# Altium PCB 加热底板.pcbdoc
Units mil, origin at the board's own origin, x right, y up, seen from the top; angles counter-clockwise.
Board outline 3503.93 x 3503.63 mil, 2 copper layers (Top Layer, Bottom Layer); 2 components, 2 nets, 6 pads, 0 vias.
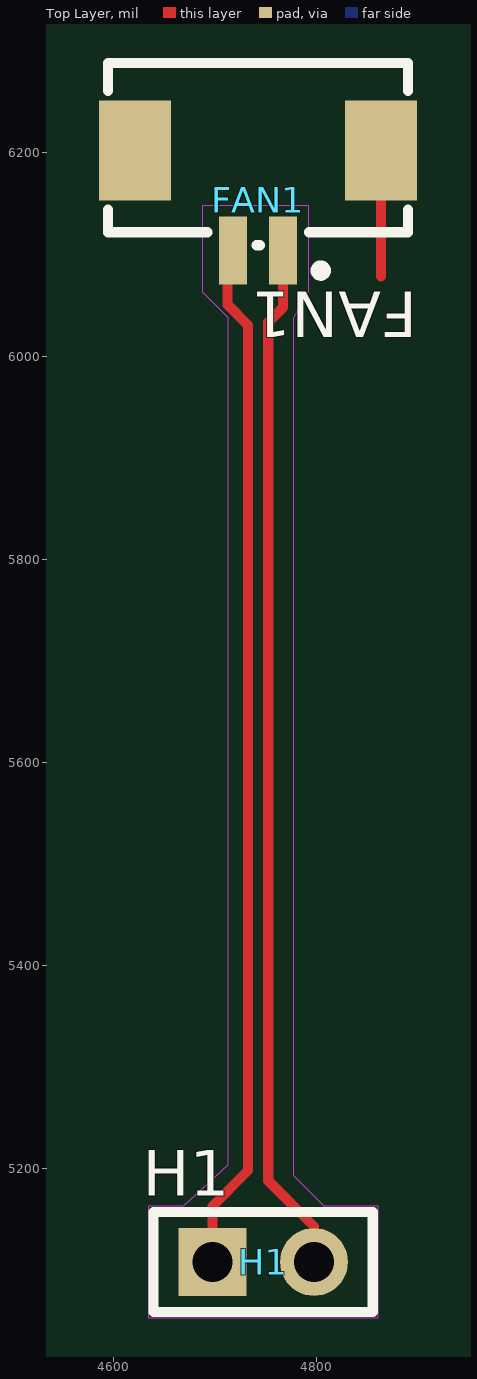
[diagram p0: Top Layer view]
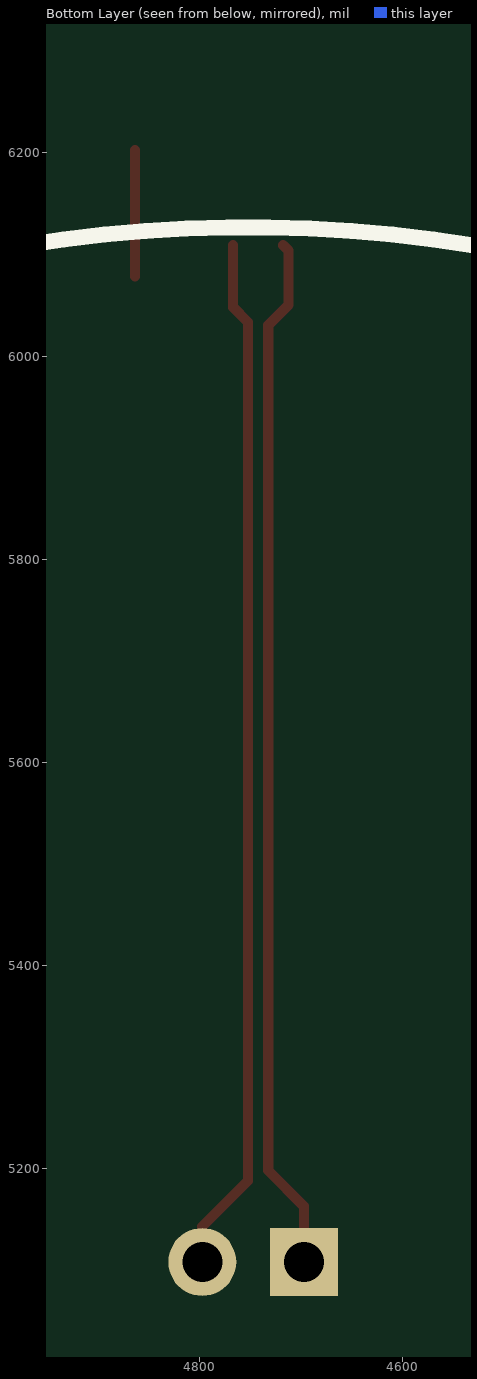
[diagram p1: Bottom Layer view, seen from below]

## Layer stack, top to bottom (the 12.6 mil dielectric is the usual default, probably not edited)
Top Layer: signal copper (thickness not stored)
Dielectric: dielectric 12.6, FR-4, Dk 4.8
Bottom Layer: signal copper (thickness not stored)

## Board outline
6503.93,4751.97 ccw(c4751.97,4751.96) 3000,4751.96 ccw(c4751.97,4751.96)

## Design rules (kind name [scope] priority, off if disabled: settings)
BoardOutlineClearance copperThickness1oz [All] p0: genericclearance=10 ignorepadtopadclearanceinfootprint=FALSE except(0: Arc-SplitContinuation Track-SplitContinuation SMDPad-SplitContinuation THPad-SplitContinuation Via-SplitContinuation Fill-SplitContinuation Poly-SplitContinuation Region-SplitContinuation Text-SplitContinuation; 6: Track-CutoutEdge SMDPad-CutoutEdge THPad-CutoutEdge Via-CutoutEdge Region-CutoutEdge; 11.8: Track-OutlineEdge SMDPad-OutlineEdge THPad-OutlineEdge Via-OutlineEdge Fill-OutlineEdge Region-OutlineEdge Poly-OutlineEdge Text-OutlineEdge Fill-CutoutEdge)
BoardOutlineClearance copperThickness2oz [All] p0: genericclearance=10 ignorepadtopadclearanceinfootprint=FALSE except(0: Arc-SplitContinuation Track-SplitContinuation SMDPad-SplitContinuation THPad-SplitContinuation Via-SplitContinuation Fill-SplitContinuation Poly-SplitContinuation Region-SplitContinuation Text-SplitContinuation; 6: Track-CutoutEdge SMDPad-CutoutEdge THPad-CutoutEdge Via-CutoutEdge Region-CutoutEdge; 11.8: Track-OutlineEdge SMDPad-OutlineEdge THPad-OutlineEdge Via-OutlineEdge Fill-OutlineEdge Region-OutlineEdge Poly-OutlineEdge Text-OutlineEdge Fill-CutoutEdge)
Clearance copperThickness1oz [(InNet('GND') OR InNet('NTC'))] p1: gap=7 ignorepadtopadclearanceinfootprint=FALSE except(4: Track-Track; 6: Track-SMDPad SMDPad-SMDPad Track-THPad SMDPad-THPad THPad-THPad Track-Via SMDPad-Via THPad-Via Via-Via SMDPad-Fill THPad-Fill Via-Fill Fill-Fill Track-Region SMDPad-Region THPad-Region Via-Region Region-Region Track-Poly SMDPad-Poly THPad-Poly Via-Poly Fill-Poly Region-Poly Poly-Poly Track-Text SMDPad-Text THPad-Text Via-Text Fill-Text Region-Text Poly-Text Text-Text; 6.9: Track-Hole SMDPad-Hole THPad-Hole Via-Hole Fill-Hole Region-Hole Poly-Hole Text-Hole Sheet-Hole; 11.8: Track-Fill Fill-Region Track-Sheet SMDPad-Sheet THPad-Sheet Via-Sheet Fill-Sheet Region-Sheet Poly-Sheet Text-Sheet)
Clearance copperThickness2oz [All] p1: gap=7 ignorepadtopadclearanceinfootprint=FALSE except(6: Track-SMDPad SMDPad-SMDPad Track-THPad SMDPad-THPad THPad-THPad Track-Via SMDPad-Via THPad-Via Via-Via SMDPad-Fill THPad-Fill Via-Fill Fill-Fill Track-Region SMDPad-Region THPad-Region Via-Region Region-Region Track-Poly SMDPad-Poly THPad-Poly Via-Poly Fill-Poly Region-Poly Poly-Poly Track-Text SMDPad-Text THPad-Text Via-Text Fill-Text Region-Text Poly-Text Text-Text; 6.9: Track-Hole SMDPad-Hole THPad-Hole Via-Hole Fill-Hole Region-Hole Poly-Hole Text-Hole Sheet-Hole; 8: Track-Track; 11.8: Track-Fill Fill-Region Track-Sheet SMDPad-Sheet THPad-Sheet Via-Sheet Fill-Sheet Region-Sheet Poly-Sheet Text-Sheet)
DiffPairsRouting differentialPair [All] p1: maxuncoupledlength=10 minlimit=6 maxlimit=6 mostfreqgap=6 toplayer_minwidth=5 toplayer_prefwidth=10 toplayer_maxwidth=100 bottomlayer_minwidth=5 bottomlayer_prefwidth=10 bottomlayer_maxwidth=100
PasteMaskExpansion pasteMaskExpansion [All] p1: expansion=0
PlaneConnect innerPlane [All] p1: planeconnectstyle=Relief reliefexpansion=20 reliefentries=4 reliefconductorwidth=10 reliefairgap=10
PolygonConnect copperRegion [All] p1: connectstyle=Relief reliefentries=4 reliefconductorwidth=10 polygonreliefangle="90 Angle" airgapwidth=10
RoutingVias viaSize [All] p1: viastyle="Through Hole" holewidth=12.0078 minholewidth=11.811 maxholewidth=248.0314 width=24.0158 minwidth=19.685 maxwidth=393.7008
SolderMaskExpansion solderMaskExpansion [All] p1: useseparateexpansions=TRUE expansion=2 expansionbottom=2
Width copperThickness1oz [All] p1: maxlimit=100 minlimit=5 preferedwidth=10
Width copperThickness2oz [All] p1: maxlimit=100 minlimit=8 preferedwidth=10

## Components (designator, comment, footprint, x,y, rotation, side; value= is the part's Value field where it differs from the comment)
FAN1 "WAFER-MX1.25-2PWB" CONN-SMD_2P-P1.25_XUNPU_WAFER-MX1.25-2PWB 4742.31,6153.31 r180 top
H1 "2.54-1*2P母" HDR-TH_2P-P2.54-V-F 4747.31,5108.31 r0 top

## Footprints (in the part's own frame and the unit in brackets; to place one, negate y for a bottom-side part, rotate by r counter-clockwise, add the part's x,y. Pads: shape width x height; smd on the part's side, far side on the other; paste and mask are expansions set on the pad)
CONN-SMD_2P-P1.25_XUNPU_WAFER-MX1.25-2PWB [mm]
  rect 0.7x1.7 smd: 1(-0.625,1.25) 2(0.625,1.25)
  rect 1.8x2.5 smd: 3(3.075,-1.25) 4(-3.075,-1.25)
  silkscreen extent -3.75,-3.43 3.75,1.88
HDR-TH_2P-P2.54-V-F [mm]
  rect 1.7x1.7 hole 1: 1(-1.27,0)
  round 1.7 hole 1: 2(1.27,0)
  silkscreen extent -2.74,-1.25 2.74,1.25

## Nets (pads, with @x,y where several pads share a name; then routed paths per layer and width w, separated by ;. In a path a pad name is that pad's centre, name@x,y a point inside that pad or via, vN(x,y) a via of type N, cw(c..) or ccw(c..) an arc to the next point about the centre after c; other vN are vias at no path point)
GND: FAN1.1 FAN1.4 H1.2 | length 1149.7
  Top Layer w10: FAN1.1@4766.92,6109.1 4766.92,6047.92 4752.31,6033.31 4752.31,5188.31 4797.31,5143.31 H1.2 ; 4863.38,6078.31 FAN1.4
NTC: FAN1.2 H1.1 | length 1025.8
  Top Layer w10: H1.1 4697.31,5163.31 4732.31,5198.31 4732.31,6030.38 4712.31,6050.38 4712.31,6103.7 FAN1.2@4717.71,6109.1
pads on no net: FAN1.3

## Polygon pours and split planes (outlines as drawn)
GND on Top Layer (solid, remove dead copper, pour order 0): 6120.67,4748.31 ccw(c4762.31,4748.31) 3403.96,4748.31 ccw(c4762.31,4748.31)

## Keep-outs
Top Layer:
  region: 4860.69,5053.59 4860.69,5163.43 4807.31,5163.31 4777.31,5193.31 4777.31,6037.71 4792.31,6063.31 4792.31,6148.14 4687.31,6148.14 4687.31,6063.31 4712.31,6038.31 4712.31,5203.5 4668.66,5163.43 4633.92,5163.43 4633.92,5053.59
Board Outline Layer:
  circle w7.87: c4751.97,4751.97 r1751.96

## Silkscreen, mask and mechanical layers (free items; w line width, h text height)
Top Silkscreen Layer:
  text "NTC B:3950 10k" at 4267.31,4873.31 h120
Bottom Silkscreen Layer:
  circle w15.75: c4751.97,4744.88 r1381.99
Mech6:
  lines w7.87: 4490.07,5593.04 cw(c4535.43,5447.38) 4687.99,5447.38 4687.99,5406.03 cw(c4535.43,5406.03) 4583.38,5261.2 ccw(c4751.97,4751.97) 4515.94,4270.26 ccw(c4535.43,4310.04) 4579.72,4310.04 4579.72,4354.35 ccw(c4535.43,4354.35) 4556.61,4393.24 cw(c4751.97,4751.97) 4406.34,4969.65 cw(c4535.43,4888.35) 4687.99,4888.35 4687.99,4751.97 ccw(c4751.97,4751.97) 4815.94,4751.97 4815.94,4888.35 cw(c4968.5,4888.35) 5097.59,4969.65 cw(c4751.97,4751.97) 4947.32,4393.25 ccw(c4968.5,4354.35) 4924.21,4354.35 4924.21,4310.04 ccw(c4968.5,4310.04) 4987.99,4270.26 ccw(c4751.96,4751.97) 4920.55,5261.2 cw(c4968.5,5406.03) 4815.94,5406.03 4815.94,5447.38 cw(c4968.5,5447.38) 5013.86,5593.04 cw(c4751.97,4751.97) 4958.13,3895.53 ccw(c4968.5,3852.47) 4924.21,3852.47 4924.21,3812.02 ccw(c4968.5,3812.02) 4978.44,3768.86 ccw(c4751.97,4751.97) 4940.06,5743.13 cw(c4968.5,5893.02) 4815.94,5893.02 4815.94,5933.06 cw(c4968.5,5933.07) 4996.01,6083.12 cw(c4751.97,4751.97) 5022.63,3425.96 5022.63,3300.45 4865.15,3300.45 4865.15,3536.67 5022.63,3536.67 ccw(c4751.97,4751.97) 4976.49,5976.63 ccw(c4968.5,5933.06) 4924.21,5933.06 4924.21,5893.02 ccw(c4968.5,5893.02) 4960.24,5849.5 cw(c4751.97,4751.97) 5002.75,3663.35 cw(c4968.5,3812.02) 4815.94,3812.02 4815.94,3852.47 cw(c4968.5,3852.47) 4932.79,4000.79 ccw(c4751.97,4751.97) 4981.67,5489.67 ccw(c4968.5,5447.38) 4924.21,5447.38 4924.21,5406.03 ccw(c4968.5,5406.03) 4954.58,5363.98 cw(c4751.96,4751.97) 5035.63,4173.04 cw(c4968.5,4310.04) 4815.94,4310.04 4815.94,4354.35 cw(c4968.5,4354.35) 4895.54,4488.33 ccw(c4751.96,4751.97) 5005.98,4911.95 ccw(c4968.5,4888.35) 4924.21,4888.35 4924.21,4751.97 cw(c4751.97,4751.97) 4579.72,4751.97 4579.72,4888.35 ccw(c4535.43,4888.35) 4497.95,4911.95 ccw(c4751.97,4751.97) 4608.39,4488.33 cw(c4535.43,4354.35) 4687.99,4354.35 4687.99,4310.04 cw(c4535.43,4310.04) 4468.3,4173.04 cw(c4751.97,4751.97) 4549.35,5363.98 ccw(c4535.43,5406.03) 4579.72,5406.03 4579.72,5447.38 ccw(c4535.43,5447.38) 4522.26,5489.67 ccw(c4751.96,4751.97) 4571.13,4000.79 cw(c4535.43,3852.47) 4687.99,3852.47 4687.99,3812.02 cw(c4535.43,3812.02) 4501.18,3663.35 cw(c4751.96,4751.97) 4543.69,5849.5 ccw(c4535.43,5893.02) 4579.72,5893.02 4579.72,5933.06 ccw(c4535.43,5933.06) 4527.44,5976.63 ccw(c4751.96,4751.97) 4481.3,3536.67 4638.78,3536.67 4638.78,3300.45 4481.3,3300.45 4481.3,3425.96 cw(c4751.96,4751.97) 4507.92,6083.12 cw(c4535.43,5933.07) 4687.99,5933.07 4687.99,5893.02 cw(c4535.43,5893.02) 4563.87,5743.13 ccw(c4751.96,4751.97) 4525.49,3768.86 ccw(c4535.43,3812.02) 4579.72,3812.02 4579.72,3852.47 ccw(c4535.43,3852.47) 4545.8,3895.53 cw(c4751.96,4751.97) 4490.08,5593.04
